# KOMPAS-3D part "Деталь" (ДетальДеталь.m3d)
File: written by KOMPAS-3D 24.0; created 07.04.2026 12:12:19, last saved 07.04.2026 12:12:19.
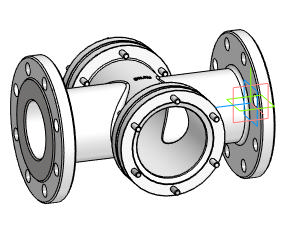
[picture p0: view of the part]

Document properties: Автор: Main; Полное имя файла: D:\DN.ru Аутсерс\Стекло смотровое DN.ru\Исходники\Стекло смотровое DN.ru SG2-34G-F тип В ГОСТ 21836-2021 Ду80 Ру16, углеродистая сталь, фланцевое\ДетальДеталь.m3d

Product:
- Body: Твердое тело1  | qty 1
- Part/product: Деталь
    additional columns: Типовые

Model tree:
1. Твердое тело1  (labels: Твердое тело1)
